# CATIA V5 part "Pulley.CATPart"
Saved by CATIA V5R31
Part number: Pulley
Bounding box of the stored display mesh (mm): x -40.838 to 40.838, y -33 to 33, z -40.838 to 40.838
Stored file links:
  D:\PROJECTS\Project 2021\US EDITION\CATIA V5 6R 2021\Resources\Part Files\c14_catia_v5_6r2021_prt\c14-catia-v5-6r2021-figr-14-26 & 27\Part & Asm\Pulley.CATPart
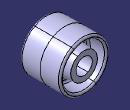
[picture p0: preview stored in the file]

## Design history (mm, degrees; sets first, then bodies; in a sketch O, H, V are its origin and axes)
Body1 (main body)
  Sketch1 on yz-plane, origin (0, 0, 0), H (0, 1, 0), V (0, 0, 1)
    line L1 (0, 13.45) -> (31.5, 13.45)
    point P1 (0, 13.45)
    point P2 (31.5, 13.45)
    line L2 (31.5, 13.45) -> (31.5, 22)
    point P3 (31.5, 22)
    line L3 (31.5, 22) -> (6, 24)
    point P4 (6, 24)
    line L4 (6, 24) -> (6, 33)
    point P5 (6, 33)
    line L5 (6, 33) -> (33, 35)
    point P6 (33, 35)
    line L6 (33, 35) -> (33, 41)
    point P7 (33, 41)
    line L7 (33, 41) -> (0, 41)
    point P8 (0, 41)
    point P9 (0, 41)
    point P10 (-33, 41)
    line L8 (-33, 41) -> (0, 41)
    point P11 (-33, 35)
    line L9 (-33, 35) -> (-33, 41)
    point P12 (-6, 33)
    line L10 (-6, 33) -> (-33, 35)
    point P13 (-6, 24)
    line L11 (-6, 24) -> (-6, 33)
    point P14 (-31.5, 22)
    line L12 (-31.5, 22) -> (-6, 24)
    point P15 (-31.5, 13.45)
    line L13 (-31.5, 13.45) -> (-31.5, 22)
    point P16 (0, 13.45)
    line L14 (0, 13.45) -> (-31.5, 13.45)
    length L1 = 31.5
    distance L1 H = 13.45
    distance P4 H = 24
    distance P3 H = 22
    distance L4 V = 6
    distance P5 H = 33
    distance P6 H = 35
    distance V L6 = 33
    distance L7 H = 41
    coincidence: P1 V, P8 V, P1 P16, P8 P9
    horizontal: L1 H, L7 H
    vertical: L2 V, L4 V, L6 V
    symmetry: P8 P9 V, P7 P10 V, L7 L8 V, P6 P11 V, L6 L9 V, P5 P12 V, L5 L10 V, P4 P13 V, L4 L11 V, P3 P14 V, L3 L12 V, P2 P15 V, L2 L13 V, P1 P16 V, L1 L14 V
  Shaft1: profile Sketch1, axis Sketch1.H, angle 360
  Fillet1: radius 3, on 4 faces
